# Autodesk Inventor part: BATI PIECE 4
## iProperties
Created: 2004-11
Part Number: BATI PIECE 4
Document SubType Name: Modeling
Designer: Bruno
Manufacturer: Standard
Standards Organization: Custom
Author: Bruno
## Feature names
1. Base1
